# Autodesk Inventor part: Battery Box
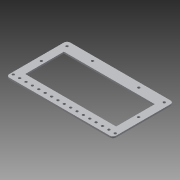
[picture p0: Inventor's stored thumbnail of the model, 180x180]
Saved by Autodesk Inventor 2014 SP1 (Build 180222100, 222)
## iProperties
Created: 2014-09
Part Number: Battery Box
Material: Aluminum 6061
Document SubType Name: Sheet Metal
Designer: Michael
Density: 2.71 g/cm^3
Sheet Metal Rule: Default
Appearance: Aluminum - Flat
Mass: 92.9807 g
Surface Area: 264.831 cm^2
Volume: 34.3102 cm^3
Author: Michael
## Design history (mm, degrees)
node "Face1"
  sketch "Sketch1"
    geometry: L1 (-89.789, -37.719)-(89.789, -37.719); L2 (89.789, -37.719)-(89.789, 37.719); L3 (89.789, 37.719)-(-89.789, 37.719); L4 (-89.789, 37.719)-(-89.789, -37.719); L5 (-89.789, -37.719)-(89.789, 37.719); L6 (89.789, -37.719)-(-89.789, 37.719); L7 (-90.583, -38.513)-(90.583, -38.513); L8 (90.583, -38.513)-(90.583, 38.513); L9 (90.583, 38.513)-(-90.583, 38.513); L10 (-90.583, 38.513)-(-90.583, -38.513); L11 (-90.583, -38.513)-(90.583, 38.513); L12 (90.583, -38.513)-(-90.583, 38.513); L13 (-106.458, -60.738)-(106.458, -60.738); L14 (106.458, -60.738)-(106.458, 60.738); L15 (106.458, 60.738)-(-106.458, 60.738); L16 (-106.458, 60.738)-(-106.458, -60.738); L17 (-106.458, -60.738)-(106.458, 60.738); L18 (106.458, -60.738)-(-106.458, 60.738); 2 further points
    constraints: 36 end point, 7 midpoint, 6 parallel, 3 horizontal, 3 perpendicular
    dimensions: "d0" = 179.578 distance of L3.end L2.end; "d1" = 75.438 distance between parallel lines of L3 L1; "d2" = 0.79375 distance between parallel lines of L3 L9; "d3" = 0.79375 distance between parallel lines of L2 L8; "d4" = 15.875 distance between parallel lines of L16 L10; "d5" = 22.225 distance between parallel lines of L13 L7
feature "Corner Round2" dims "d10" = 6.35
sketch "Sketch4"
  geometry: L1 (-100.108, 60.738)-(100.108, 60.738) reference; L2 (-106.458, -54.388)-(-106.458, 54.388) reference; L3 (-90.583, -38.513)-(-90.583, 38.513) reference; C1 r 2.489 at (-96.933, 51.213); C2 r 2.489 at (-46.133, 51.213); C3 r 2.489 at (-96.933, 0); 2 further points
  constraints: 3 centre point, 2 horizontal alignment, 1 midpoint, 1 vertical alignment
  dimensions: "d33" = 4.9784 diameter of C1; "d34" = 9.525 distance from line of L1 C1.centre; "d35" = 9.525 distance from line of L2 C1.centre (= d34); "d38" = 4.9784 diameter of C2 (= d33); "d39" = 50.8 distance of C2.centre C1.centre; "d40" = 4.9784 diameter of C3 (= d38)
cut "Cut2" sketch "Sketch4" dims "d36" = 3.175 (= Thickness), "d37" = 0
mirror "Mirror2"
sketch "Sketch5"
  geometry: L1 (-100.108, 60.738)-(100.108, 60.738) reference; C1 r 2.489 at (0, 51.213); 1 further point
  constraints: 1 centre point
  dimensions: "d41" = 4.9784 diameter of C1; "d42" = 9.525 distance from line of L1 C1.centre; "d43" = 0 horizontal distance of point (0, 0) C1.centre
hole "Hole2" sketch "Sketch5" at (0, 51.213) diameter "d44" = 4.9784; stored, may be unused: countersink angle "d48" = 82 deg, drill point angle "d50" = 118 deg; dims "d45" = 19.05, "d46" = 9.525, "d47" = 6.35, "d49" = 3.175 (= Thickness)
body "Solid1"
pattern_linear "Rectangular Pattern3" dims "d53" = 12.7, "d56" = 12.7
face "Plate1" dims "Thickness" = 3.175 (derived)
other parameters: "KFactor" = 4.4, "BendRadius" = 3.175 (= Thickness), "BendReliefWidth" = 3.175 (= Thickness), "BendReliefDepth" = 1.5875 (= 0.5 x Thickness), "CornerReliefSize" = 12.7 (= 4 x Thickness), "SeamGap" = 0.00508, "MinimumRemnant" = 6.35 (= 2 x Thickness), "TransitionRadius" = 3.175 (= BendRadius), "JacobiRadiusSize" = 3.175 (= Thickness), "GapSize" = 3.175 (= Thickness), "d8" = 3.175 (= BendRadius)
